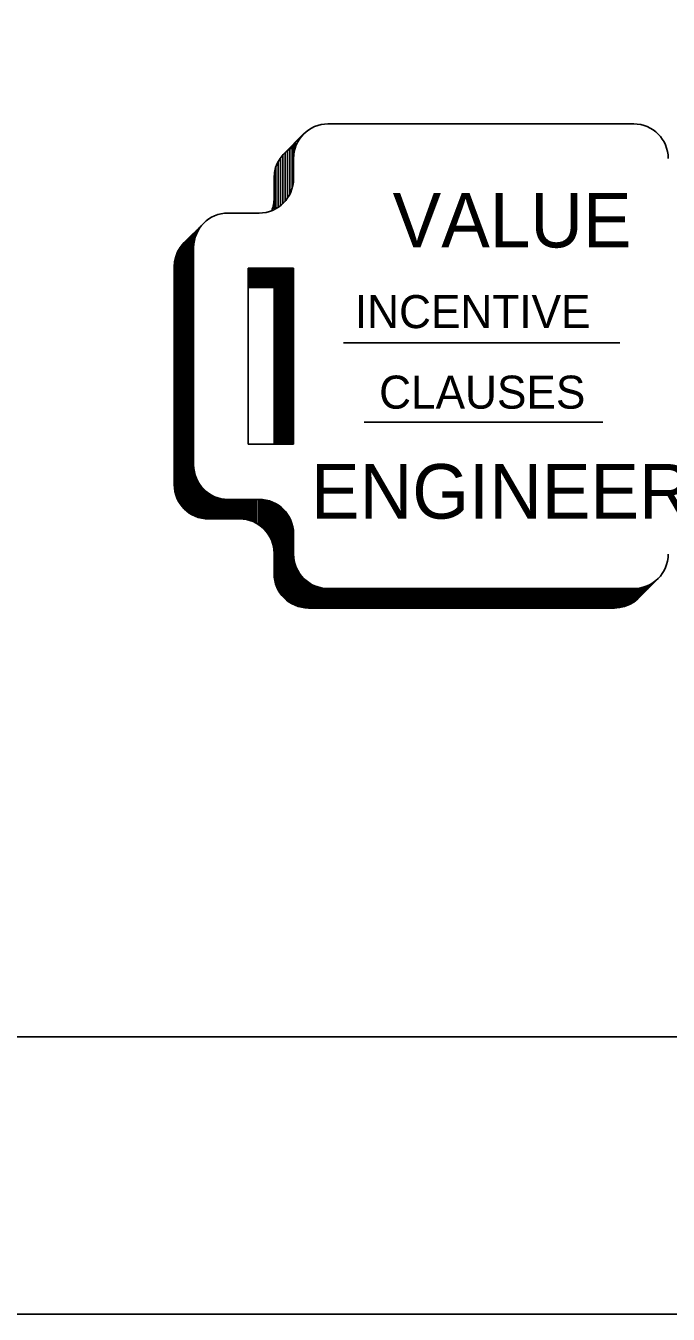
# Model space of a CAD drawing. Extents: x 22411.4 to 22495.4, y 22369.6 to 22415.
# Drawn here: x 22439.511 to 22441.067, y 22369.621 to 22372.741 of the extents above; entities that cross this region are included whole.
import ezdxf

# ---------------------------------------------------------------- set-up
doc = ezdxf.new("R2010")
doc.units = 0
for name, color, linetype in [('Level 1', 7, 'Continuous'), ('Level 2', 7, 'Continuous'), ('Level 7', 7, 'Continuous'), ('Level 9', 7, 'Continuous')]:
    doc.layers.add(name, color=color, linetype=linetype)

msp = doc.modelspace()

# ---------------------------------------------------------------- linework, layer by layer
at = {"layer": 'Level 1'}
msp.add_lwpolyline([(22436.7229, 22414.9653), (22495.39, 22414.9653), (22495.39, 22369.6213), (22436.7229, 22369.6213)], close=True, dxfattribs=at)
at = {"layer": 'Level 2'}
for p, q in [((22440.1366, 22372.432), (22440.1837, 22372.4792)), ((22440.1719, 22372.464), (22440.1719, 22372.4673)), ((22440.1754, 22372.4693), (22440.1754, 22372.4708)), ((22440.1387, 22372.4342), (22440.1387, 22372.316)), ((22440.1444, 22372.4398), (22440.1444, 22372.3233)), ((22440.1504, 22372.4458), (22440.1504, 22372.3333)), ((22440.1561, 22372.4515), (22440.1561, 22372.3477)), ((22440.1594, 22372.4202), (22440.1594, 22372.4548)), ((22440.1634, 22372.4457), (22440.1634, 22372.4588)), ((22440.1677, 22372.4565), (22440.1677, 22372.4632)), ((22440.1224, 22372.4128), (22440.1224, 22372.3017)), ((22440.1276, 22372.4212), (22440.1276, 22372.3055)), ((22440.1332, 22372.4283), (22440.1332, 22372.3103)), ((22440.1122, 22372.373), (22440.1122, 22372.296)), ((22440.1167, 22372.4), (22440.1167, 22372.2983)), ((22439.8946, 22372.2162), (22439.9417, 22372.2633)), ((22439.9251, 22372.2392), (22439.9251, 22372.2467)), ((22439.9266, 22372.2423), (22439.9266, 22372.2482)), ((22439.9282, 22372.2455), (22439.9282, 22372.2498)), ((22439.9299, 22372.2482), (22439.9299, 22372.2515)), ((22439.9316, 22372.2508), (22439.9316, 22372.2532)), ((22439.9332, 22372.2532), (22439.9332, 22372.2548)), ((22439.8949, 22372.2163), (22439.8949, 22371.5713)), ((22439.8977, 22372.2193), (22439.8977, 22371.5687)), ((22439.8997, 22372.2213), (22439.8997, 22371.5668)), ((22439.9019, 22372.2235), (22439.9019, 22371.5652)), ((22439.9046, 22372.2262), (22439.9046, 22371.5632)), ((22439.9074, 22372.229), (22439.9074, 22371.5612)), ((22439.9097, 22372.2313), (22439.9097, 22371.5597)), ((22439.9119, 22372.2335), (22439.9119, 22371.5583)), ((22439.9141, 22372.2357), (22439.9141, 22371.5572)), ((22439.9156, 22372.2372), (22439.9156, 22371.5563)), ((22439.9174, 22372.2043), (22439.9174, 22372.239)), ((22439.9192, 22372.2217), (22439.9192, 22372.2408)), ((22439.9216, 22372.2303), (22439.9216, 22372.2432)), ((22439.9234, 22372.2353), (22439.9234, 22372.245)), ((22439.8751, 22372.1852), (22439.8751, 22371.6025)), ((22439.8777, 22372.1917), (22439.8777, 22371.596)), ((22439.8799, 22372.1962), (22439.8799, 22371.5915)), ((22439.8826, 22372.2008), (22439.8826, 22371.5868)), ((22439.8852, 22372.2048), (22439.8852, 22371.5828)), ((22439.8881, 22372.2087), (22439.8881, 22371.579)), ((22439.8904, 22372.2115), (22439.8904, 22371.5762)), ((22439.8926, 22372.214), (22439.8926, 22371.5737)), ((22439.8702, 22372.1572), (22439.8702, 22371.6305)), ((22439.8726, 22372.1767), (22439.8726, 22371.611)), ((22440.1594, 22372.1543), (22440.1122, 22372.1072)), ((22440.1594, 22372.1522), (22440.0491, 22372.1522)), ((22440.1594, 22372.15), (22440.0491, 22372.15)), ((22440.1594, 22372.1475), (22440.0491, 22372.1475)), ((22440.1594, 22372.145), (22440.0491, 22372.145)), ((22440.1594, 22372.1423), (22440.0491, 22372.1423)), ((22440.1594, 22372.1398), (22440.0491, 22372.1398)), ((22440.1594, 22372.1373), (22440.0491, 22372.1373)), ((22440.1594, 22372.1347), (22440.0491, 22372.1347)), ((22440.1594, 22372.1323), (22440.0491, 22372.1323)), ((22440.1594, 22372.1298), (22440.0491, 22372.1298)), ((22440.1594, 22372.1273), (22440.0491, 22372.1273)), ((22440.1594, 22372.125), (22440.0491, 22372.125)), ((22440.1594, 22372.1227), (22440.0491, 22372.1227)), ((22440.1594, 22372.1207), (22440.0491, 22372.1207)), ((22440.1594, 22372.1182), (22440.0491, 22372.1182)), ((22440.1594, 22372.1162), (22440.0491, 22372.1162)), ((22440.1594, 22372.114), (22440.0491, 22372.114)), ((22440.1594, 22372.112), (22440.0491, 22372.112)), ((22440.1594, 22372.1095), (22440.0491, 22372.1095)), ((22440.1122, 22372.1072), (22440.0491, 22372.1072)), ((22440.1122, 22371.7277), (22440.1122, 22372.1072)), ((22440.1146, 22371.7277), (22440.1146, 22372.1095)), ((22440.1164, 22371.7277), (22440.1164, 22372.1095)), ((22440.1184, 22371.7277), (22440.1184, 22372.1095)), ((22440.1201, 22371.7277), (22440.1201, 22372.1095)), ((22440.1226, 22371.7277), (22440.1226, 22372.1095)), ((22440.1247, 22371.7277), (22440.1247, 22372.1095)), ((22440.1271, 22371.7277), (22440.1271, 22372.1095)), ((22440.1287, 22371.7277), (22440.1287, 22372.1095)), ((22440.1314, 22371.7277), (22440.1314, 22372.1095)), ((22440.1336, 22371.7277), (22440.1336, 22372.1095)), ((22440.1354, 22371.7277), (22440.1354, 22372.1095)), ((22440.1376, 22371.7277), (22440.1376, 22372.1095)), ((22440.1397, 22371.7277), (22440.1397, 22372.1095)), ((22440.1422, 22371.7277), (22440.1422, 22372.1095)), ((22440.1442, 22371.7277), (22440.1442, 22372.1095)), ((22440.1462, 22371.7277), (22440.1462, 22372.1095)), ((22440.1487, 22371.7277), (22440.1487, 22372.1095)), ((22440.1512, 22371.7277), (22440.1512, 22372.1095)), ((22440.1537, 22371.7277), (22440.1537, 22372.1095)), ((22440.1554, 22371.7277), (22440.1554, 22372.1095)), ((22440.1576, 22371.7277), (22440.1576, 22372.1095)), ((22439.9186, 22371.6638), (22439.9186, 22371.5548)), ((22439.9212, 22371.6527), (22439.9212, 22371.5537)), ((22439.9237, 22371.6458), (22439.9237, 22371.5527)), ((22439.9262, 22371.6403), (22439.9262, 22371.5518)), ((22439.9292, 22371.6348), (22439.9292, 22371.5508)), ((22439.9314, 22371.6315), (22439.9314, 22371.5502)), ((22439.9336, 22371.6283), (22439.9336, 22371.5497)), ((22439.9364, 22371.6247), (22439.9364, 22371.549)), ((22439.9387, 22371.622), (22439.9387, 22371.5485)), ((22439.9412, 22371.6193), (22439.9412, 22371.5482)), ((22439.9437, 22371.6168), (22439.9437, 22371.5477)), ((22439.9462, 22371.6147), (22439.9462, 22371.5475)), ((22439.9486, 22371.6127), (22439.9486, 22371.5473)), ((22439.9514, 22371.6105), (22439.9514, 22371.5472)), ((22439.9539, 22371.6087), (22439.9539, 22371.5472)), ((22439.9564, 22371.6072), (22439.9564, 22371.5472)), ((22439.9589, 22371.6057), (22439.9589, 22371.5472)), ((22439.9619, 22371.604), (22439.9619, 22371.5472)), ((22439.9641, 22371.6028), (22439.9641, 22371.5472)), ((22439.9654, 22371.6022), (22439.9654, 22371.5472)), ((22439.9676, 22371.6012), (22439.9676, 22371.5472)), ((22439.9697, 22371.6003), (22439.9697, 22371.5472)), ((22439.9724, 22371.5993), (22439.9724, 22371.5472)), ((22439.9751, 22371.5983), (22439.9751, 22371.5472)), ((22439.9776, 22371.5977), (22439.9776, 22371.5472)), ((22439.9809, 22371.5967), (22439.9809, 22371.5472)), ((22439.9839, 22371.596), (22439.9839, 22371.5472)), ((22439.9864, 22371.5955), (22439.9864, 22371.5472)), ((22439.9882, 22371.5953), (22439.9882, 22371.5472)), ((22439.9907, 22371.595), (22439.9907, 22371.5472)), ((22439.9929, 22371.5947), (22439.9929, 22371.5472)), ((22439.9947, 22371.5945), (22439.9947, 22371.5472)), ((22439.9971, 22371.5943), (22439.9971, 22371.5472)), ((22439.9997, 22371.5943), (22439.9997, 22371.5472)), ((22440.0022, 22371.5943), (22440.0022, 22371.5472)), ((22440.0051, 22371.5943), (22440.0051, 22371.5472)), ((22440.0079, 22371.5943), (22440.0079, 22371.5472)), ((22440.0104, 22371.5943), (22440.0104, 22371.5472)), ((22440.0137, 22371.5943), (22440.0137, 22371.5472)), ((22440.0166, 22371.5943), (22440.0166, 22371.5472)), ((22440.0191, 22371.5943), (22440.0191, 22371.5472)), ((22440.0219, 22371.5943), (22440.0219, 22371.5472)), ((22440.0251, 22371.5943), (22440.0251, 22371.5472)), ((22440.0281, 22371.5943), (22440.0281, 22371.5472)), ((22440.0312, 22371.5943), (22440.0312, 22371.5472)), ((22440.0344, 22371.5943), (22440.0344, 22371.5472)), ((22440.0381, 22371.5943), (22440.0381, 22371.5467)), ((22440.0406, 22371.5943), (22440.0406, 22371.5463)), ((22440.0427, 22371.5943), (22440.0427, 22371.546)), ((22440.0449, 22371.5943), (22440.0449, 22371.5457)), ((22440.0484, 22371.5943), (22440.0484, 22371.5448)), ((22440.0521, 22371.5943), (22440.0521, 22371.5438)), ((22440.0559, 22371.5943), (22440.0559, 22371.5427)), ((22440.0596, 22371.5943), (22440.0596, 22371.5413)), ((22440.0627, 22371.5943), (22440.0627, 22371.54)), ((22440.0664, 22371.5943), (22440.0664, 22371.5383)), ((22440.0692, 22371.5943), (22440.0692, 22371.5368)), ((22440.0736, 22371.5943), (22440.0736, 22371.5342)), ((22440.0771, 22371.5943), (22440.0771, 22371.5318)), ((22440.0789, 22371.5943), (22440.0789, 22371.5305)), ((22440.0821, 22371.5943), (22440.0821, 22371.528)), ((22440.0846, 22371.5938), (22440.0846, 22371.5258)), ((22440.0872, 22371.5935), (22440.0872, 22371.5233)), ((22440.0897, 22371.5932), (22440.0897, 22371.5208)), ((22440.0916, 22371.5928), (22440.0916, 22371.5188)), ((22440.0944, 22371.5923), (22440.0944, 22371.5153)), ((22440.0972, 22371.5917), (22440.0972, 22371.5115)), ((22440.1002, 22371.5908), (22440.1002, 22371.5068)), ((22440.1031, 22371.5898), (22440.1031, 22371.5018)), ((22440.1056, 22371.589), (22440.1056, 22371.4965)), ((22440.1082, 22371.5878), (22440.1082, 22371.4893)), ((22440.1111, 22371.5867), (22440.1111, 22371.4777)), ((22440.1132, 22371.5857), (22440.1132, 22371.4018)), ((22440.1159, 22371.5842), (22440.1159, 22371.3902)), ((22440.1186, 22371.5827), (22440.1186, 22371.3828)), ((22440.1211, 22371.5812), (22440.1211, 22371.3773)), ((22440.1236, 22371.5795), (22440.1236, 22371.3727)), ((22440.1261, 22371.5777), (22440.1261, 22371.3687)), ((22440.1289, 22371.5755), (22440.1289, 22371.3647)), ((22440.1311, 22371.5737), (22440.1311, 22371.3618)), ((22440.1336, 22371.5713), (22440.1336, 22371.359)), ((22440.1357, 22371.5692), (22440.1357, 22371.3567)), ((22440.1384, 22371.5663), (22440.1384, 22371.354)), ((22440.1409, 22371.5633), (22440.1409, 22371.3518)), ((22439.9536, 22371.5472), (22440.0289, 22371.5472)), ((22440.1437, 22371.5597), (22440.1437, 22371.3493)), ((22440.1464, 22371.5557), (22440.1464, 22371.3473)), ((22440.1486, 22371.5522), (22440.1486, 22371.3458)), ((22440.1506, 22371.5483), (22440.1506, 22371.3445)), ((22440.1522, 22371.5448), (22440.1522, 22371.3435)), ((22440.1544, 22371.5395), (22440.1544, 22371.3422)), ((22440.1562, 22371.5338), (22440.1562, 22371.3412)), ((22440.1577, 22371.5275), (22440.1577, 22371.3403)), ((22440.1122, 22371.4638), (22440.1122, 22371.4147)), ((22440.1596, 22371.4565), (22440.1596, 22371.3395)), ((22440.1619, 22371.4415), (22440.1619, 22371.3385)), ((22440.1641, 22371.4343), (22440.1641, 22371.3375)), ((22440.1659, 22371.4295), (22440.1659, 22371.3368)), ((22440.1679, 22371.4252), (22440.1679, 22371.336)), ((22440.1696, 22371.422), (22440.1696, 22371.3355)), ((22440.1719, 22371.418), (22440.1719, 22371.3348)), ((22440.1741, 22371.4147), (22440.1741, 22371.3342)), ((22440.1764, 22371.4113), (22440.1764, 22371.3335)), ((22440.1781, 22371.4093), (22440.1781, 22371.3332)), ((22440.1804, 22371.4065), (22440.1804, 22371.3327)), ((22440.1817, 22371.405), (22440.1817, 22371.3325)), ((22440.1836, 22371.4032), (22440.1836, 22371.3322)), ((22440.1856, 22371.4012), (22440.1856, 22371.332)), ((22440.1871, 22371.3998), (22440.1871, 22371.3318)), ((22440.1881, 22371.399), (22440.1881, 22371.3317)), ((22440.1892, 22371.398), (22440.1892, 22371.3315)), ((22440.1911, 22371.3965), (22440.1911, 22371.3315)), ((22440.1934, 22371.3947), (22440.1934, 22371.3315)), ((22440.1961, 22371.3928), (22440.1961, 22371.3315)), ((22440.1984, 22371.3913), (22440.1984, 22371.3315)), ((22440.2011, 22371.3897), (22440.2011, 22371.3315)), ((22440.2036, 22371.3883), (22440.2036, 22371.3315)), ((22440.2061, 22371.387), (22440.2061, 22371.3315)), ((22440.2081, 22371.386), (22440.2081, 22371.3315)), ((22440.2104, 22371.385), (22440.2104, 22371.3315)), ((22440.2131, 22371.384), (22440.2131, 22371.3315)), ((22440.2157, 22371.383), (22440.2157, 22371.3315)), ((22440.2184, 22371.3822), (22440.2184, 22371.3315)), ((22440.2212, 22371.3813), (22440.2212, 22371.3315)), ((22440.2242, 22371.3805), (22440.2242, 22371.3315)), ((22440.2266, 22371.38), (22440.2266, 22371.3315)), ((22440.2296, 22371.3795), (22440.2296, 22371.3315)), ((22440.2322, 22371.3792), (22440.2322, 22371.3315)), ((22440.2349, 22371.3788), (22440.2349, 22371.3315)), ((22440.2381, 22371.3787), (22440.2381, 22371.3315)), ((22440.2407, 22371.3785), (22440.2407, 22371.3315)), ((22440.2407, 22371.3773), (22440.9362, 22371.3773)), ((22440.2407, 22371.3765), (22440.9362, 22371.3765)), ((22440.2407, 22371.3757), (22440.9362, 22371.3757)), ((22440.2407, 22371.3745), (22440.9362, 22371.3745)), ((22440.2407, 22371.3732), (22440.9362, 22371.3732)), ((22440.9362, 22371.3313), (22440.9362, 22371.3785)), ((22440.9381, 22371.3313), (22440.9381, 22371.3785)), ((22440.9394, 22371.3313), (22440.9394, 22371.3785)), ((22440.9407, 22371.3315), (22440.9407, 22371.3785)), ((22440.9429, 22371.3317), (22440.9429, 22371.3785)), ((22440.9446, 22371.3318), (22440.9446, 22371.3785)), ((22440.9466, 22371.332), (22440.9466, 22371.3785)), ((22440.9482, 22371.3322), (22440.9482, 22371.3785)), ((22440.9501, 22371.3325), (22440.9501, 22371.3785)), ((22440.9516, 22371.3328), (22440.9516, 22371.3785)), ((22440.9536, 22371.3332), (22440.9536, 22371.3785)), ((22440.9554, 22371.3335), (22440.9554, 22371.3785)), ((22440.9572, 22371.334), (22440.9572, 22371.3785)), ((22440.9596, 22371.3347), (22440.9596, 22371.3785)), ((22440.9621, 22371.3355), (22440.9621, 22371.3785)), ((22440.9641, 22371.3362), (22440.9641, 22371.3785)), ((22440.9661, 22371.3368), (22440.9661, 22371.3785)), ((22440.9682, 22371.3377), (22440.9682, 22371.3785)), ((22440.9704, 22371.3387), (22440.9704, 22371.3785)), ((22440.9722, 22371.3395), (22440.9722, 22371.3785)), ((22440.9747, 22371.3408), (22440.9747, 22371.3785)), ((22440.9772, 22371.3422), (22440.9772, 22371.3785)), ((22440.9796, 22371.3435), (22440.9796, 22371.3785)), ((22440.9819, 22371.345), (22440.9819, 22371.3785)), ((22440.9842, 22371.3465), (22440.9842, 22371.3785)), ((22440.9864, 22371.3482), (22440.9864, 22371.3785)), ((22440.9887, 22371.35), (22440.9887, 22371.3785)), ((22440.9912, 22371.352), (22440.9912, 22371.3788)), ((22440.9936, 22371.3542), (22440.9936, 22371.3792)), ((22440.9952, 22371.3557), (22441.0424, 22371.4028)), ((22440.9956, 22371.356), (22440.9956, 22371.3793)), ((22440.9977, 22371.3582), (22440.9977, 22371.3797)), ((22440.9994, 22371.3598), (22440.9994, 22371.38)), ((22441.0014, 22371.3618), (22441.0014, 22371.3805)), ((22441.0031, 22371.3635), (22441.0031, 22371.3808)), ((22441.0049, 22371.3653), (22441.0049, 22371.3813)), ((22441.0069, 22371.3673), (22441.0069, 22371.3818)), ((22441.0082, 22371.3687), (22441.0082, 22371.3823)), ((22441.0099, 22371.3703), (22441.0099, 22371.3828)), ((22441.0114, 22371.3718), (22441.0114, 22371.3833)), ((22441.0131, 22371.3735), (22441.0131, 22371.384)), ((22441.0141, 22371.3745), (22441.0141, 22371.3843)), ((22441.0161, 22371.3765), (22441.0161, 22371.3852)), ((22441.0176, 22371.378), (22441.0176, 22371.3858)), ((22441.0192, 22371.3797), (22441.0192, 22371.3867)), ((22441.0211, 22371.3815), (22441.0211, 22371.3875)), ((22441.0226, 22371.383), (22441.0226, 22371.3883)), ((22441.0241, 22371.3845), (22441.0241, 22371.3892)), ((22441.0256, 22371.386), (22441.0256, 22371.39)), ((22441.0272, 22371.3877), (22441.0272, 22371.391)), ((22441.0289, 22371.3893), (22441.0289, 22371.392)), ((22441.0304, 22371.3908), (22441.0304, 22371.393)), ((22441.0319, 22371.3923), (22441.0319, 22371.394)), ((22441.0334, 22371.3938), (22441.0334, 22371.3952)), ((22440.2407, 22371.3717), (22440.9362, 22371.3717)), ((22440.2407, 22371.3702), (22440.9362, 22371.3702)), ((22440.2407, 22371.3688), (22440.9362, 22371.3688)), ((22440.2407, 22371.3673), (22440.9362, 22371.3673)), ((22440.2407, 22371.3658), (22440.9362, 22371.3658)), ((22440.2407, 22371.3643), (22440.9362, 22371.3643)), ((22440.2407, 22371.3628), (22440.9362, 22371.3628)), ((22440.2407, 22371.3613), (22440.9362, 22371.3613)), ((22440.2407, 22371.36), (22440.9362, 22371.36)), ((22440.2407, 22371.3585), (22440.9362, 22371.3585)), ((22440.2407, 22371.3572), (22440.9362, 22371.3572)), ((22440.2407, 22371.3558), (22440.9362, 22371.3558)), ((22440.2407, 22371.3543), (22440.9362, 22371.3543)), ((22440.2407, 22371.3528), (22440.9362, 22371.3528)), ((22440.2407, 22371.3512), (22440.9362, 22371.3512)), ((22440.2407, 22371.3495), (22440.9362, 22371.3495)), ((22440.2407, 22371.3478), (22440.9362, 22371.3478)), ((22440.2407, 22371.3463), (22440.9362, 22371.3463)), ((22440.2407, 22371.3445), (22440.9362, 22371.3445)), ((22440.2407, 22371.3428), (22440.9362, 22371.3428)), ((22440.1956, 22371.3313), (22440.9362, 22371.3313)), ((22440.2407, 22371.341), (22440.9362, 22371.341)), ((22440.2407, 22371.3392), (22440.9362, 22371.3392)), ((22440.2407, 22371.3372), (22440.9362, 22371.3372)), ((22440.2407, 22371.3353), (22440.9362, 22371.3353)), ((22440.2407, 22371.3335), (22440.9362, 22371.3335))]:
    msp.add_line(p, q, dxfattribs=at)
for centre, start, end in [((22440.1955, 22372.3729), 111.4079, 180), ((22440.0288, 22372.3238), 338.5921, 0), ((22439.9535, 22372.1571), 111.4079, 180), ((22439.9535, 22371.6304), 180, 270), ((22440.0288, 22371.4638), 0, 90), ((22440.1955, 22371.4146), 180, 270), ((22440.9362, 22371.4146), 270, 338.5921)]:
    msp.add_arc(centre, 0.0833, start, end, dxfattribs=at)
at = {"layer": 'Level 7'}
for p, q in [((22440.9834, 22372.5035), (22440.2427, 22372.5035)), ((22440.1594, 22372.4202), (22440.1594, 22372.371)), ((22440.0761, 22372.2877), (22440.0007, 22372.2877)), ((22439.9174, 22372.2043), (22439.9174, 22371.6777)), ((22440.1594, 22372.1543), (22440.0491, 22372.1543)), ((22440.0491, 22371.7277), (22440.0491, 22372.1543)), ((22440.1594, 22371.7277), (22440.1594, 22372.1543)), ((22440.2802, 22371.9732), (22440.9494, 22371.9732)), ((22440.3306, 22371.7812), (22440.9081, 22371.7812)), ((22440.1594, 22371.7277), (22440.0491, 22371.7277)), ((22440.0007, 22371.5943), (22440.0761, 22371.5943)), ((22440.1594, 22371.511), (22440.1594, 22371.4618)), ((22440.2427, 22371.3785), (22440.9834, 22371.3785))]:
    msp.add_line(p, q, dxfattribs=at)
for centre, start, end in [((22440.2427, 22372.4201), 90, 180), ((22440.9833, 22372.4201), 0, 90), ((22440.076, 22372.3709), 270, 0), ((22440.0007, 22372.2043), 90, 180), ((22440.0007, 22371.6776), 180, 270), ((22440.076, 22371.5109), 0, 90), ((22440.2427, 22371.4618), 180, 270), ((22440.9833, 22371.4618), 270, 0)]:
    msp.add_arc(centre, 0.0833, start, end, dxfattribs=at)
at = {"layer": 'Level 9'}
msp.add_line((22438.7229, 22370.2933), (22491.054, 22370.2933), dxfattribs=at)

# ---------------------------------------------------------------- texts
at = {"layer": 'Level 2'}
for s, height, p in [('VALUE', 0.13199, (22440.3992, 22372.2043)), ('INCENTIVE', 0.08, (22440.3079, 22372.009)), ('CLAUSES', 0.08, (22440.3666, 22371.814)), ('ENGINEERING', 0.13199, (22440.2016, 22371.5478))]:
    msp.add_text(s, height=height, dxfattribs=at).set_placement(p)

doc.saveas('drawing.dxf')
